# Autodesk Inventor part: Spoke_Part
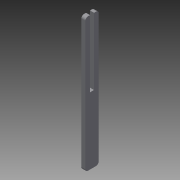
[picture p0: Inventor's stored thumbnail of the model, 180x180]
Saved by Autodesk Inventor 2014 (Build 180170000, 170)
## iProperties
Created: 2014-06
Part Number: Spoke_Part
Material: Generic
Document SubType Name: Modeling
Designer: Aser
Density: 1 g/cm^3
Appearance: Default
Author: Aser
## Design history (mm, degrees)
sketch "Sketch1"
  geometry: L1 (-5, 50)-(5, 50); L2 (5, 50)-(5, -50); L3 (5, -50)-(-5, -50); L4 (-5, -50)-(-5, 50); L5 (-5, 50)-(5, -50); L6 (5, 50)-(-5, -50); L7 (1.5, 50)-(-1.5, 50); L8 (-1.5, 50)-(-1.5, 0); L9 (-1.5, 0)-(1.5, 0); L10 (1.5, 0)-(1.5, 50); 1 further point
  constraints: 20 end point, 4 parallel, 2 horizontal, 2 midpoint, 2 perpendicular, 1 point on line
  dimensions: "d0" = 10 distance of L2.end L3.end; "d1" = 100 distance of L1.end L2.end; "d2" = 50 distance of L9.end L7.start; "d3" = 3 distance of L8.end L9.end; "d4" = 3.5 distance between parallel lines of L2 L10
extrude "Extrusion1" new body sketch "Sketch1" distance "d5" = 3; taper "d6" = 0 deg
fillet "Fillet1" dims "d7" = 2
body "Solid1"
